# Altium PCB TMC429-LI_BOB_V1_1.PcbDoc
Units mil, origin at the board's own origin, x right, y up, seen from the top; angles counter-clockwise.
Board outline 1000 x 1000 mil, 4 copper layers (Top, GND, SPLY, Bottom), stack 27.719 mil thick; 31 components, 30 nets, 97 pads, 39 vias.
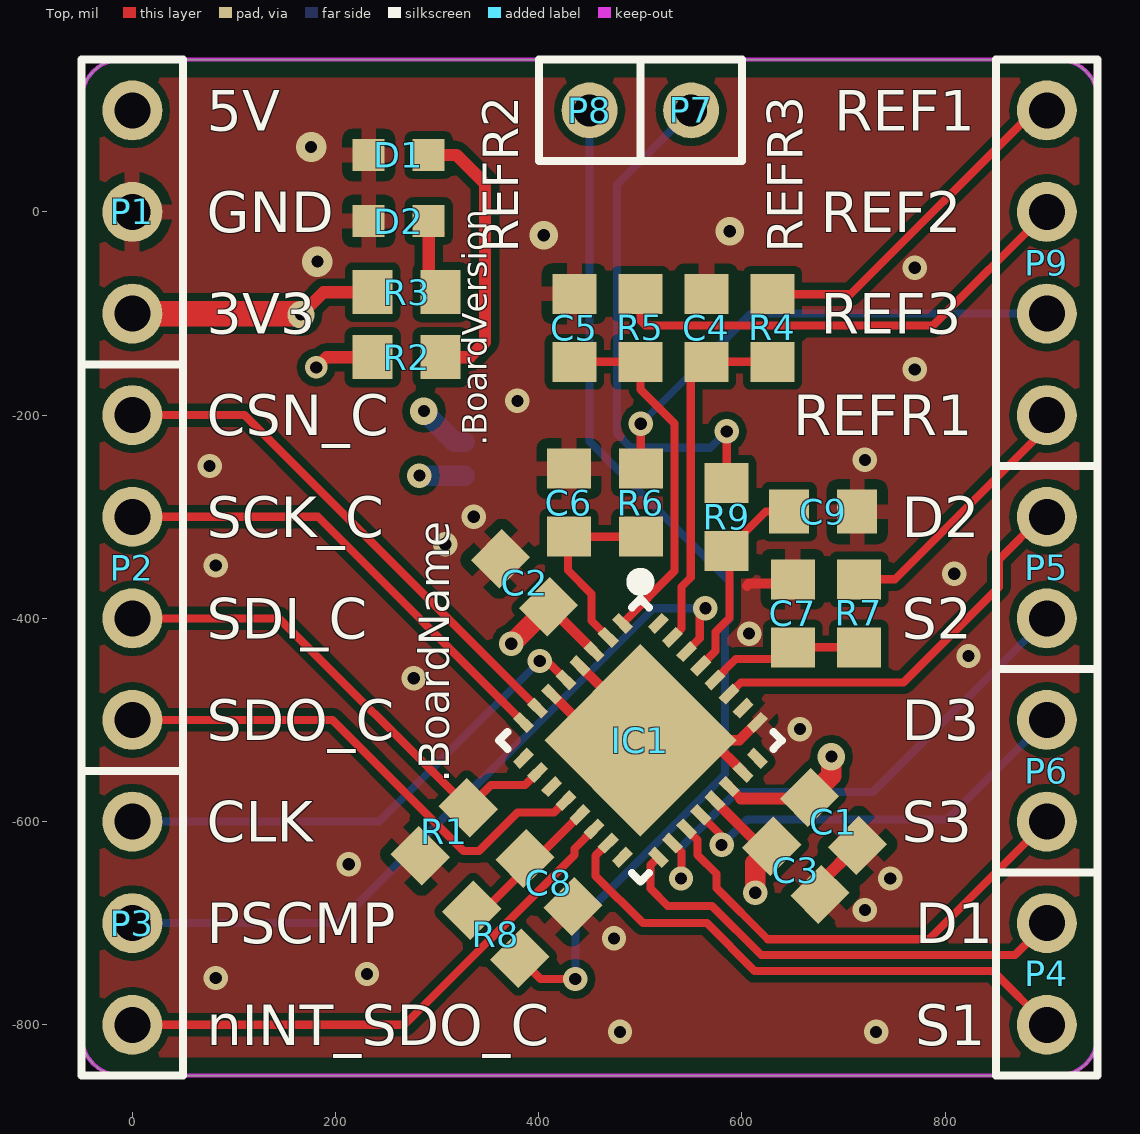
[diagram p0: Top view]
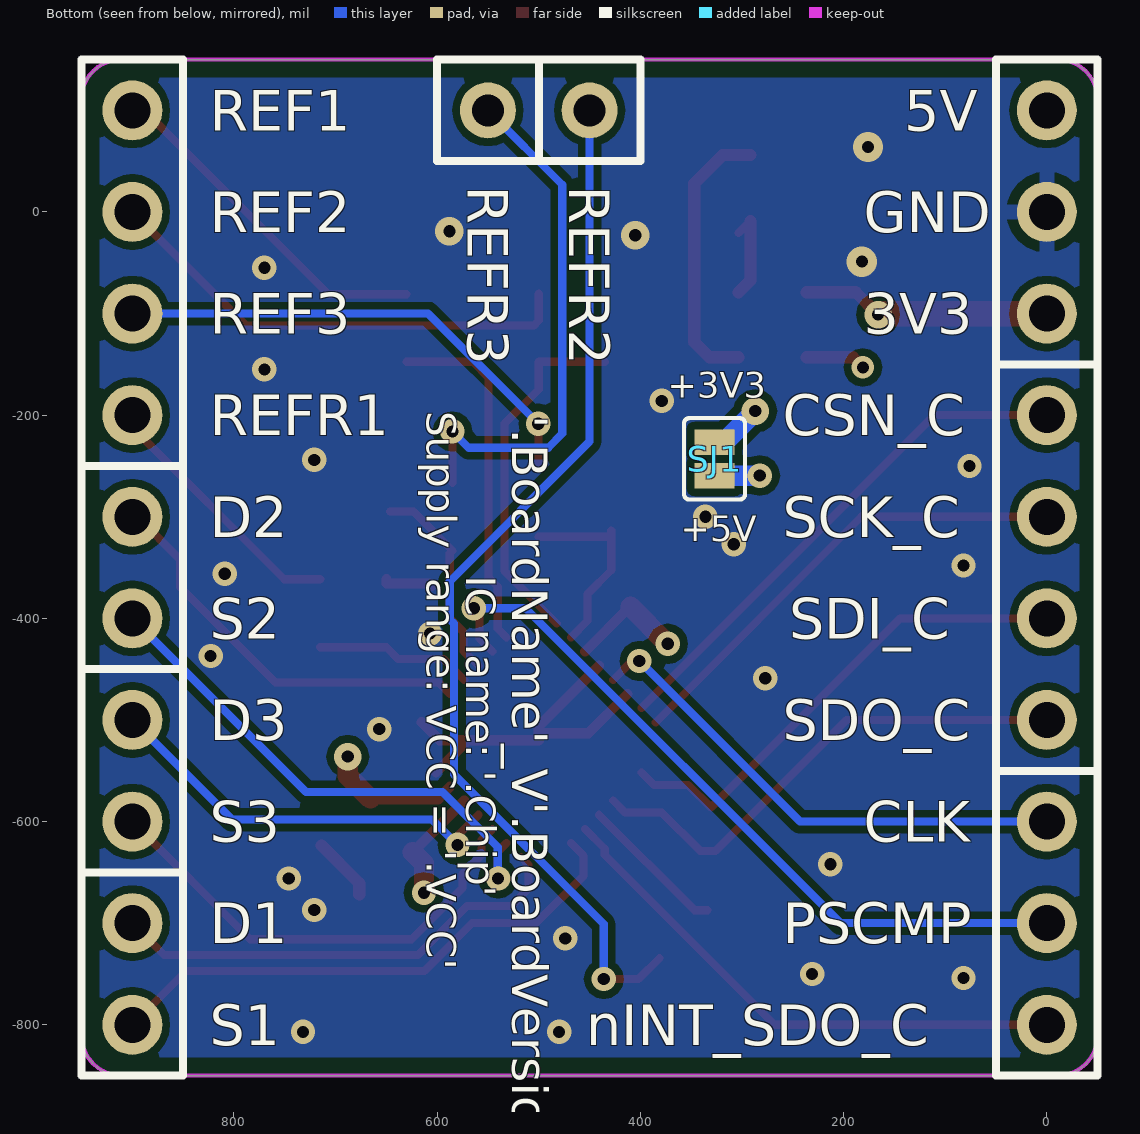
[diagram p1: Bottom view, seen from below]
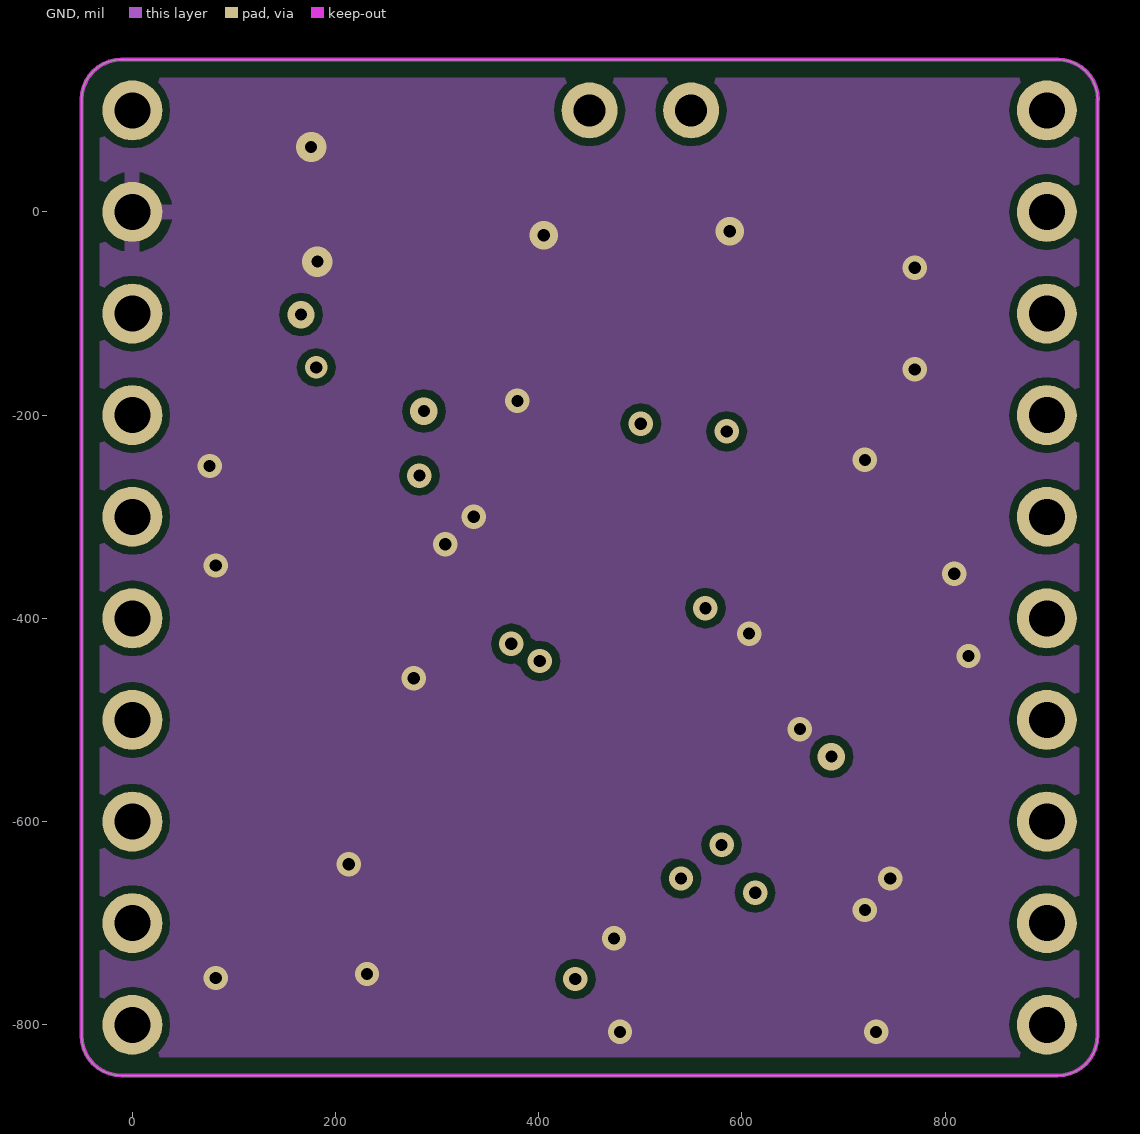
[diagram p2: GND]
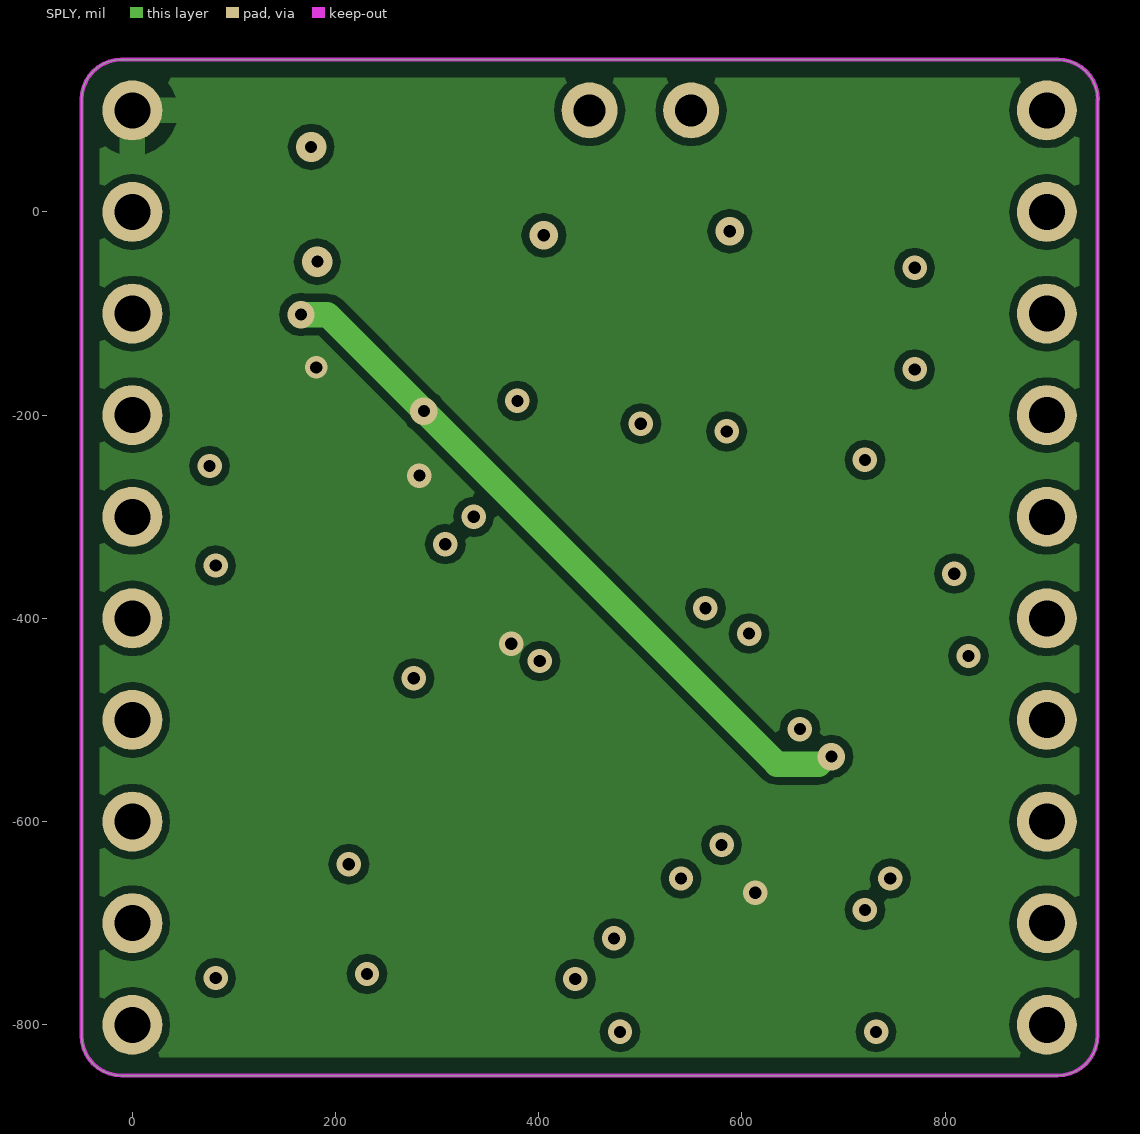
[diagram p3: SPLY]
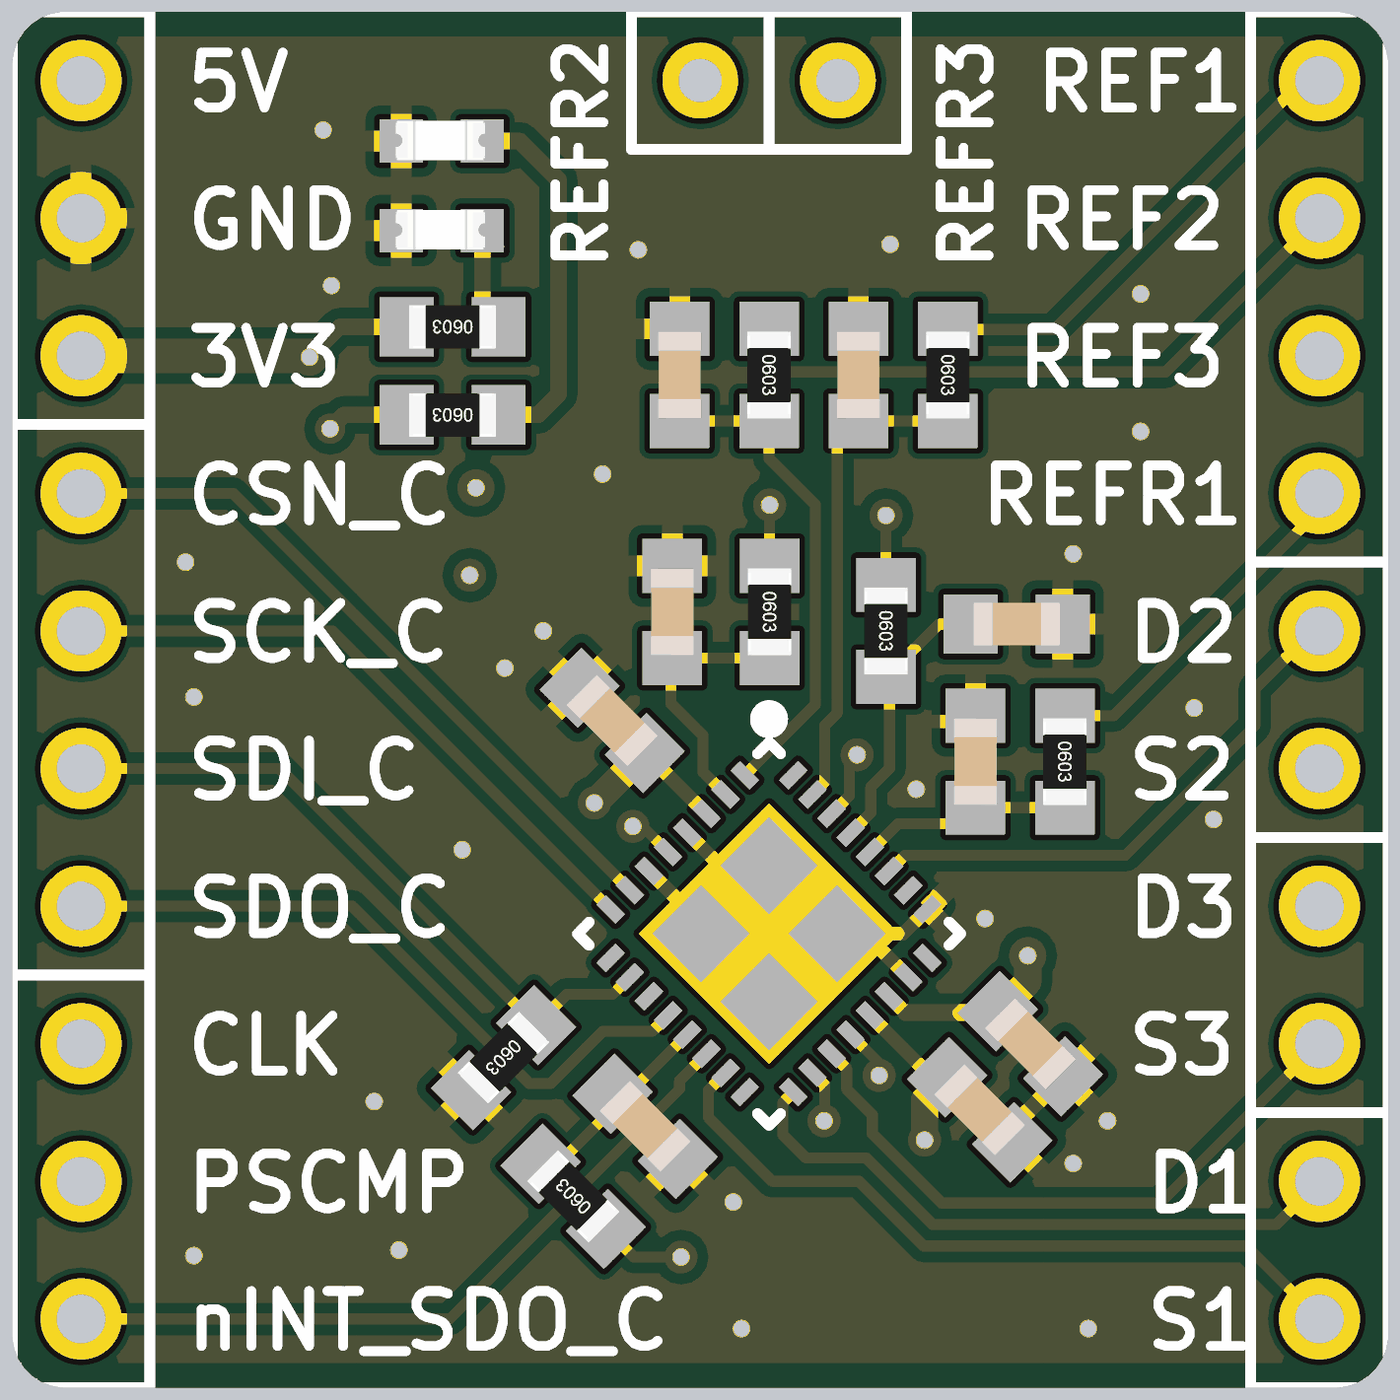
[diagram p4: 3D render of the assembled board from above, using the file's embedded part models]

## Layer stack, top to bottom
Top Solder: solder mask 0.4, Solder Resist, Dk 3.5
Top: signal copper 1.378
Dielectric 1: core 7.874, FR-4, Dk 4.8
GND: signal copper 0.689
Dielectric 2: prepreg 5, FR-4, Dk 4.2
SPLY: signal copper 1.4
Dielectric4: core 10, FR-4, Dk 4.2
Bottom: signal copper 1.378
Bottom Solder: solder mask 0.4, Solder Resist, Dk 3.5

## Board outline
-50,-810.63 ccw(c-10.63,-810.63) -10.63,-850 910.63,-850 ccw(c910.63,-810.63) 950,-810.63 950,110.63 ccw(c910.63,110.63) 910.63,150 -10.63,150 ccw(c-10.63,110.63) -50,110.63

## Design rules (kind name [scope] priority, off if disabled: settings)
Clearance BoardOutlineClearance [OnLayer('Keep-Out Layer')] p1: gap=15.75 ignorepadtopadclearanceinfootprint=FALSE except(0: Arc-Hole Track-Hole SMDPad-Hole THPad-Hole Via-Hole Fill-Hole Poly-Hole Region-Hole Text-Hole)
Clearance "Fiducial Clearance" [HasFootprint('FIDUCIAL_40MIL')] p2: gap=26 ignorepadtopadclearanceinfootprint=FALSE except(0: Arc-Hole Track-Hole SMDPad-Hole THPad-Hole Via-Hole Fill-Hole Poly-Hole Region-Hole Text-Hole)
Clearance [All] p3: gap=7.6 ignorepadtopadclearanceinfootprint=FALSE except(0: Arc-Hole Track-Hole SMDPad-Hole THPad-Hole Via-Hole Fill-Hole Poly-Hole Region-Hole Text-Hole)
ComponentClearance Pinheader2PinheaderClearance [InComponentClass('Pinheader') vs InComponentClass('Pinheader')] p1: gap=0 collisioncheckmode=3 verticalgap=0 showdistances=FALSE
ComponentClearance [All] p2: gap=10 collisioncheckmode=3 verticalgap=10 showdistances=FALSE
DiffPairsRouting [All] p1 off: maxlimit=10 minlimit=7.5 mostfreqgap=10 toplayer_prefgap=7.5 toplayer_minwidth=7.5 toplayer_maxwidth=7.5 toplayer_prefwidth=7.5 midlayer1_prefgap=7.5 midlayer1_minwidth=7.5 midlayer1_maxwidth=7.5 midlayer1_prefwidth=7.5 midlayer2_mingap=10 midlayer2_minwidth=15 midlayer2_maxwidth=15 midlayer2_prefwidth=15 bottomlayer_prefgap=7.5 bottomlayer_minwidth=7.5 bottomlayer_maxwidth=7.5 bottomlayer_prefwidth=7.5 maxuncoupledlength=500
HoleSize [All] p1: absolutevalues=TRUE maxlimit=100000 minlimit=11.81 maxpercent=80.000 minpercent=20.000
HoleToHoleClearance [All] p1: gap=8 allowstackedmicrovias=TRUE
MatchedLengths "SD_CARD MatchedLengths" [InNetClass('SD_CARD')] p1: tolerance=10 checknetsindiffpair=FALSE checkdiffpairvsdiffpair=TRUE checkxsignals=TRUE checkothers=TRUE
MinimumAnnularRing MinimumViaAnnualRing [All] p1: minimumring=4.92
MinimumSolderMaskSliver STM32_MinimumSolderMaskSliver [(InComponent('STM1') AND InComponent('STM2')) vs (InComponent('STM1') AND InComponent('STM2'))] p1: minsoldermaskwidth=1
MinimumSolderMaskSliver USB_HUB_MinimumSolderMaskSliver [InComponent('USB_HUB')] p2: minsoldermaskwidth=1
MinimumSolderMaskSliver [All] p3 off: minsoldermaskwidth=1.5
PasteMaskExpansion TestPadPasteMaskExpansion [HasFootprint('SMD_TP_2X2_ROUND')] p1: expansion=-78.74
PasteMaskExpansion [All] p2: expansion=0
PlaneConnect VM_PlaneConnect [OnLayer('VM') AND InNet('VM')] p1: planeconnectstyle=Relief reliefexpansion=20 reliefentries=4 reliefconductorwidth=20 reliefairgap=10
PlaneConnect [All] p2: planeconnectstyle=Relief reliefexpansion=20 reliefentries=4 reliefconductorwidth=10 reliefairgap=10
PolygonConnect VSA_C1_ConnectStyle [InNet('VM') AND inComponent('C1')] p1: connectstyle=Direct reliefconductorwidth=20 reliefentries=4 polygonreliefangle="90 Angle" airgapwidth=8
PolygonConnect ViaConnectStyle [IsVia] p2: connectstyle=Direct reliefconductorwidth=20 reliefentries=4 polygonreliefangle="90 Angle" airgapwidth=8
PolygonConnect 5V_ConnectStyle [InNet('+5V')] p3: connectstyle=Relief reliefconductorwidth=25 reliefentries=4 polygonreliefangle="90 Angle" airgapwidth=15
PolygonConnect MotorPhaceConnectStyle [(IsVia OR IsPad) AND InNetClass('MotorPower')] p4: connectstyle=Direct reliefconductorwidth=10 reliefentries=4 polygonreliefangle="90 Angle" airgapwidth=10
PolygonConnect ThermalVias [IsVia] p5: connectstyle=Direct reliefconductorwidth=10 reliefentries=4 polygonreliefangle="90 Angle" airgapwidth=10
PolygonConnect [All] p6: connectstyle=Relief reliefconductorwidth=15 reliefentries=4 polygonreliefangle="90 Angle" airgapwidth=10
RoutingVias [All] p1: holewidth=12 width=24 viastyle="Through Hole" minholewidth=12 minwidth=22 maxholewidth=12 maxwidth=50
ShortCircuit [All] p1 off: allowed=FALSE
SilkToBoardRegionClearance [All] p1 off:
SilkToSilkClearance [All] p1 off: silktosilkclearance=10
SilkToSolderMaskClearance [IsPad] p1 off: minsilkscreentomaskgap=10 clearancetoexposedcopper=TRUE
SolderMaskExpansion FiducialSolderMaskExpansion [HasFootprint('FIDUCIAL_40MIL')] p1: expansion=26
SolderMaskExpansion [All] p2: expansion=4
UnRoutedNet [All] p1 off:
Width Other_Width [All] p1: maxlimit=100000 minlimit=8 preferedwidth=11.81 minimp=50.000000 maximp=50.000000 favimp=50.000000
18 further rules are at their usual default settings.

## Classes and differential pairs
differential pair class USB_DIFF: STM_USB STM_USB_D

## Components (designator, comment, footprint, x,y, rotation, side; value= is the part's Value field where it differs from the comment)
C1 "470nF/16V/10%" C0603 690,-600 r315 top
C2 "100nF/16V/10%" C0603 386,-365 r135 top
C3 "100nF/16V/10%" C0603 653,-648 r315 top
C4 "10nF/16V/10%" C0603 565,-114 r90 top
C5 "10nF/16V/10%" C0603 435,-114 r90 top
C6 "10nF/16V/10%" C0603 429.72,-286.17 r90 top
C7 "10nF/16V/10%" C0603 650.01,-395 r90 top
C8 "10nF/16V/10%" C0603 410,-660 r315 top
C9 "10nF/16V/10%" C0603 680,-295 r0 top
D1 "LED, Blue, SMD, 20mA, 2.8V, 465 nm" LED_0603 262.13,56 r180 top
D2 "LED, Blue, SMD, 20mA, 2.8V, 465 nm" LED_0603 262.13,-9 r180 top
IC1 "TMC429-LI" TMC429_QFN32_0.5_5.0X5.0 500,-520 r225 top
P1 "PWR" 3_PIN_THT 0,-100 r0 top
P2 "SPI" 4_PIN_THT 0,-200 r180 top
P3 "MISC" 3_PIN_THT 0,-800 r0 top
P4 "S/D_1" 2_PIN_THT 900,-800 r0 top
P5 "S/D_2" 2_PIN_THT 900,-400 r0 top
P6 "S/D_3" 2_PIN_THT 900,-600 r0 top
P7 "REFR3" TH_PIN 550,100 r0 top
P8 "REFR2" TH_PIN 450,100 r0 top
P9 "REF" 4_PIN_THT 900,-200 r0 top
R1 "10k" R0603 307,-610 r225 top
R2 "1k" R0603 270.01,-142.99 r180 top
R3 "1k" R0603 270.01,-78.99 r180 top
R4 "4k7" R0603 630,-114 r270 top
R5 "4k7" R0603 500,-114 r270 top
R6 "4k7" R0603 500.43,-286.17 r270 top
R7 "4k7" R0603 715.01,-395 r270 top
R8 "4k7" R0603 357.68,-710.9 r135 top
R9 "4k7" R0603 585,-300 r270 top
SJ1 "SPI_MODE" SJ_SMALL_2PIN_1X0.635 327,-243 r270 bottom

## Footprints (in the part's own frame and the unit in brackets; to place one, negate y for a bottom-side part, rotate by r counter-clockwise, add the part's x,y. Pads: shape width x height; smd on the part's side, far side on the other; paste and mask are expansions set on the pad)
2_PIN_THT [mm]
  round 1.5 hole 0.9: 1(0,0) 2(0,2.54)
  silkscreen extent -1.27,-1.27 1.27,3.81
3_PIN_THT [mm]
  round 1.5 hole 0.9: 1(0,0) 2(0,2.54) 3(0,5.08)
  silkscreen extent -1.27,-1.27 1.27,6.35
4_PIN_THT [mm]
  round 1.5 hole 0.9: 1(0,0) 2(0,2.54) 3(0,5.08) 4(0,7.62)
  silkscreen extent -1.27,-1.27 1.27,8.89
C0603 [mm] "0603 ceramic capacitor"
  rect 1x1.1 smd: 1(-0.85,0) 2(0.85,0)
  body extent -0.8,-0.4 0.8,0.4, height 0.8
LED_0603 [mm]
  rect 0.8x0.8 smd: 1(-0.75,0) 2(0.75,0)
  body extent -0.8,-0.38 0.85,0.35, height 0.68
R0603 [mm] "0603 resistor"
  rect 1x1.1 smd: 1(-0.85,0) 2(0.85,0)
  body extent -0.8,-0.4 0.8,0.4, height 0.45
SJ_SMALL_2PIN_1X0.635 [mil]
  rect 25x39.37 smd: 1(-16.5,0) 2(16.5,0)
  silkscreen extent -40,-30 40,30
TH_PIN [mm]
  round 1.4 hole 0.8: 1(0,0)
  silkscreen extent -1.27,-1.27 1.27,1.27
TMC429_QFN32_0.5_5.0X5.0 [mm]
  rect 0.254x0.5 smd: 1(-1.75,-2.385) 2(-1.25,-2.385) 3(-0.75,-2.385) 4(-0.25,-2.385) 5(0.25,-2.385) 6(0.75,-2.385) 7(1.25,-2.385) 8(1.75,-2.385) 17(1.75,2.385) 18(1.25,2.385) 19(0.75,2.385) 20(0.25,2.385) 21(-0.25,2.385) 22(-0.75,2.385) 23(-1.25,2.385) 24(-1.75,2.385)
  rect 0.5x0.254 smd: 9(2.385,-1.75) 10(2.385,-1.25) 11(2.385,-0.75) 12(2.385,-0.25) 13(2.385,0.25) 14(2.385,0.75) 15(2.385,1.25) 16(2.385,1.75) 25(-2.385,1.75) 26(-2.385,1.25) 27(-2.385,0.75) 28(-2.385,0.25) 29(-2.385,-0.25) 30(-2.385,-0.75) 31(-2.385,-1.25) 32(-2.385,-1.75)
  rect 3.4x3.4 smd paste-25.4: 33(0,0)
  silkscreen extent -2.9,-2.9 2.5,2.5, body extent -2.5,-2.5 2.5,2.5, height 0.9

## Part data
C1: library part Capacitor, "Ceramic capacitor", Capacitance=470nF, MPN=MC0603X474K160CT, VoltageRating=16V
C2 C3: library part Capacitor, "Ceramic capacitor", Capacitance=100nF, MPN=MC0603B104K160CT, VoltageRating=16V
C4 C5 C6 C7 C8 C9: library part Capacitor, "Ceramic capacitor", Capacitance=10nF, MPN=MC0603B103K160CT, VoltageRating=16V
D1 D2: Colour=Blue, Current rating=20mA, MPN=LTST-C191TBKT-5A
IC1: "Intelligent Triple Stepper Motor Controller with SPI, Step/Dir, QFN32(5x5)"
P1 P3: library part "Header 3", "Header, 3-Pin"
P2 P9: library part "Header 4", "Header, 4-Pin"
P4 P5 P6: library part "Header 2", "Header, 2-Pin"
P7 P8: library part PIN
R1: library part "10 kohm, 50 V, 0603 [1608 Metric], 63 mW, ± 1%, MC Series", "10 kohm, 50 V, 0603 [1608 Metric], 63 mW, ± 1%, MC Series", MPN=MC0063W0603110K, PowerRating=63mW, Temp coefficient=*ppm, VoltageRating=50V
R2 R3: library part "1 kohm, 50 V, 0603 [1608 Metric], 63 mW, ± 1%, MC Series", "1 kohm, 50 V, 0603 [1608 Metric], 63 mW, ± 1%, MC Series", MPN=MC0063W060311K, PowerRating=63mW, Temp coefficient=*ppm, VoltageRating=50V
R4 R5 R6 R7 R8 R9: library part "4.7 kohm, 50 V, 0603 [1608 Metric], 63 mW, ± 1%, MC Series", "4.7 kohm, 50 V, 0603 [1608 Metric], 63 mW, ± 1%, MC Series", MPN=MC0063W060314K7, PowerRating=63mW, Temp coefficient=*ppm, VoltageRating=50V
SJ1: library part SJ, "SMD solder <b>JUMPER</b>"

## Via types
v1: diameter 24, hole 12, Top to Bottom, tented both sides, 31 vias
v2: diameter 27, hole 12, Top to Bottom, tented both sides, 3 vias
v3: diameter 29.81, hole 11.81, Top to Bottom, tented both sides, 2 vias
v4: diameter 28, hole 12, Top to Bottom, tented both sides, 2 vias
v5: diameter 22, hole 12, Top to Bottom, tented both sides, 1 vias

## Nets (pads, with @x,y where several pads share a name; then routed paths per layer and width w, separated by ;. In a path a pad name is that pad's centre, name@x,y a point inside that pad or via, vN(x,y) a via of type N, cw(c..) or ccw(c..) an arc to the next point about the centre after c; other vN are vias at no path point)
+3V3: C1.1 IC1.22 P1.1 R3.2 SJ1.1 | length 1125.3
  Top w10: IC1.22 599.1,-577.34
  Top w12: v2(166,-101) 188.01,-78.99 R3.2 ; 599.1,-577.34 C1.1@665.66,-577.34
  Top w20: C1.1@665.66,-577.34 688,-555 v2(688,-536)
  Top w25: P1.1 165,-100 v2(166,-101)
  SPLY w25: v2(166,-101) 192,-101 v2(287,-196) 634.43,-543.43 675.43,-543.43
  Bottom w20: v2(287,-196) 317.5,-226.5 SJ1.1
+5V: C2.1 C3.1 IC1.3 IC1.21 P1.3 R2.2 SJ1.2 | length 335.1
  Top w8: v1(373,-425) v1@373.33,-425 ; C2.1 C2.1@410.42,-388.66
  Top w10: C2.1@410.42,-388.66 IC1.3 ; IC1.21 C3.1@624,-630.08
  Top w12: v5(181,-153) 191.01,-142.99 R2.2
  Top w20: v1@373.33,-425 C2.1 ; v1(613,-670) 613,-641.08 C3.1@624,-630.08
  Bottom w20: v1(282.5,-259.5) SJ1.2
CLK: IC1.5 P3.3 | length 499.8
  Top w8: v1(401,-442) 408.08,-442 IC1.5
  Bottom w8: P3.3 243,-600 v1(401,-442)
CSN_C: IC1.7 P2.1 | length 518.3
  Top w8: P2.1 110.4,-200 IC1.7
D1: IC1.17 P4.2 | length 464.2
  Top w8: IC1.17 510,-642.79 510,-666 527,-683 570.56,-683 618.96,-731.4 868.6,-731.4 P4.2
D2: IC1.27 P5.2 | length 400.8
  Top w8: IC1.27 598.76,-463 759,-463 853,-369 853,-342 895,-300 P5.2
D3: IC1.20 P6.2 | length 409.1
  Top w8: IC1.20 580,-613.92 v1(580,-623)
  Bottom w8: v1(580,-623) 605,-598 802,-598 P6.2
GND: C1.2 C2.2 C3.2 C4.2 C5.2 C6.2 C7.2 C8.2 C9.2 D1.2 D2.2 IC1.4 IC1.6 IC1.23 IC1.25 IC1.33 P1.2 R1.2 | length 481.8
  Top w10: IC1.6 451.28,-513.04 IC1.33@500,-513.04 ; IC1.4 500,-506.08 IC1.33@500,-513.04 ; IC1.23 IC1.33@569.6,-520 ; 605,-368 607.25,-365.75 650.01,-365.75 C7.2 ; IC1.25 597.44,-520 IC1.33@569.6,-520 ; IC1.33@500,-513.04 IC1.33 555.68,-520 IC1.33@569.6,-520
  Top w12: C3.2 676.66,-660.66 C1.2
  other v1: 480,-807 732,-807 82,-754 231,-750 474,-715 721,-687 746,-656 213,-642 657,-509 277,-459 823,-437 607,-415 809,-356 82,-348 308,-327 336,-300 76,-250 721,-244 379,-186 770,-155 770,-55
  other v3: 182,-49 176,64
  other v4: 405,-23 588,-19
NetD1_1: D1.1 R2.1 | length 272.7
  Top w12: D1.1 319,56 347,28 347,-128 332.01,-142.99 R2.1
NetD2_1: D2.1 R3.1 | length 91.6
  Top w8: D2.1 D2.1@303.47,-20.81
  Top w12: D2.1 291.66,-67.18 R3.1
NINT_SDO_C: IC1.14 P3.1 | length 538
  Top w8: P3.1 268,-800 435,-633 435,-626.76 IC1.14
PSCMP: IC1.30 P3.2 | length 742.8
  Top w8: IC1.30 558.4,-419.84 558.4,-395.6 v1(564,-390)
  Bottom w8: P3.2 203,-700 513,-390 v1(564,-390)
REF1: C4.1 IC1.31 R4.2 | length 350.2
  Top w8: IC1.31 540.4,-410 540.4,-368.87 549.6,-359.67 549.6,-162.86 C4.1 R4.2
REF1IN: P9.4 R4.1 | length 345
  Top w8: R4.1@630,-81 707,-81 888,100 P9.4
REF2: C5.1 IC1.1 R5.2 | length 357.7
  Top w8: C5.1 R5.2 500,-174.62 533.68,-208.31 533.68,-353.53 IC1.1
REF2IN: P9.3 R5.1 | length 474.8
  Top w8: R5.1 500,-107 504.82,-111.82 788.18,-111.82 P9.3
REF3: C6.1 IC1.2 R6.2 | length 192.3
  Top w8: C6.1@428.67,-313.66 428.67,-352.67 452,-376 452,-402.4 IC1.2 ; C6.1 R6.2
REF3IN: P9.2 R6.1 | length 488.8
  Top w8: R6.1 v1(500.43,-208.43)
  Bottom w8: v1(500.43,-208.43) 608.86,-100 P9.2
REFR1: C7.1 IC1.28 R7.2 | length 154.9
  Top w8: IC1.28 593.92,-440 638.47,-440 C7.1 R7.2
REFR1IN: P9.1 R7.1 | length 258.9
  Top w8: R7.1 750.47,-361.53 900,-212 P9.1
REFR2: C8.1 IC1.13 R8.2 | length 145.4
  Top w8: R8.2 346.68,-687.24 IC1.13
REFR2IN: P8.1 R8.1 | length 1037.9
  Top w8: R8.1 401.78,-755 v1(436,-755)
  Bottom w8: v1(436,-755) 436,-701 583.4,-553.6 583.4,-405.22 587.6,-401.02 587.6,-363.6 450,-226 P8.1
REFR3: C9.1 IC1.29 R9.2 | length 203.4
  Top w8: IC1.29 574,-432.08 574,-413.38 587.6,-399.78 587.6,-336.06 R9.2 623.46,-295 C9.1
REFR3IN: P7.1 R9.1 | length 519.6
  Top w8: R9.1 v1(585,-216)
  Bottom w8: P7.1 476.83,26.83 476.83,-218.2 490.65,-232.03 568.97,-232.03 v1(585,-216)
S1: IC1.15 P4.1 | length 542.1
  Top w8: IC1.15 456,-633.6 456,-653.44 502.56,-700 565.5,-700 612.5,-747 847,-747 P4.1
S2: IC1.18 P5.1 | length 522.4
  Top w8: IC1.18 540.4,-630 540.4,-649.6 540,-650 v1(540,-656)
  Bottom w8: v1(540,-656) 540,-650 540.4,-649.6 540.4,-625.22 594.62,-571 729,-571 P5.1
S3: IC1.19 P6.1 | length 476.9
  Top w8: IC1.19 556.4,-618.16 556.4,-632.78 575,-651.38 575,-665.38 625.42,-715.8 784.2,-715.8 P6.1
  Bottom w8: P6.1@897,-598 P6.1@906,-607
SCK_C: IC1.8 P2.2 | length 468.7
  Top w8: P2.2 182.56,-300 IC1.8
SDI_C: IC1.10 P2.3 R1.1 | length 490.4
  Top w8: P2.3 144.33,-400 R1.1 353,-564 386.4,-564 IC1.10
SDO_C: IC1.12 P2.4 | length 500.6
  Top w8: P2.4 197,-500 326,-629 341,-629 379,-591 415.08,-591 IC1.12
pads on no net: IC1.9 IC1.11 IC1.16 IC1.24 IC1.26 IC1.32

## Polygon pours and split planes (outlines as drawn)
GND on Bottom "BTM_GND" (solid, pour order 8): -50,-810.63 -50,110.63 cw(c-10.63,110.63) -10.63,150 910.63,150 910.97,150 cw(c910.97,110.63) 950.34,110.63 950,110.63 950,-810.63 cw(c910.63,-810.63) 910.63,-850 -10.63,-850 cw(c-10.63,-810.63)
GND on GND "BTM_GND" (solid, pour order 7): -50,-810.63 -50,110.63 cw(c-10.63,110.63) -10.63,150 910.63,150 910.97,150 cw(c910.97,110.63) 950.34,110.63 950,110.63 950,-810.63 cw(c910.63,-810.63) 910.63,-850 -10.63,-850 cw(c-10.63,-810.63)
GND on Top "BTM_GND" (solid, pour order 6): -50,-810.63 -50,110.63 cw(c-10.63,110.63) -10.63,150 910.63,150 910.97,150 cw(c910.97,110.63) 950.34,110.63 950,110.63 950,-810.63 cw(c910.63,-810.63) 910.63,-850 -10.63,-850 cw(c-10.63,-810.63)
+5V on SPLY "BTM_GND" (solid, pour order 5): -50,-810.63 -50,110.63 cw(c-10.63,110.63) -10.63,150 910.63,150 910.97,150 cw(c910.97,110.63) 950.34,110.63 950,110.63 950,-810.63 cw(c910.63,-810.63) 910.63,-850 -10.63,-850 cw(c-10.63,-810.63)

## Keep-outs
Keep-Out Layer:
  the board outline again, w4

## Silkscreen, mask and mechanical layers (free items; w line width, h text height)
Top Overlay:
  text "5V" at 73.45,80.01 h40
  text "REF1" at 690.71,80.01 h40
  text "GND" at 73.45,-19.99 h40
  text "REF2" at 677.38,-19.99 h40
  text "REFR2" at 380,-40 h35 r90
  text "REFR3" at 660,-40 h35 r90
  text "3V3" at 73.45,-119.99 h40
  text "REF3" at 677.38,-119.99 h40
  text "CSN_C" at 73.45,-219.99 h40
  text "REFR1" at 650.72,-219.99 h40
  text ".BoardVersion" at 349,-230.11 h24 r90
  text "SCK_C" at 73.45,-319.99 h40
  text "D2" at 757.35,-319.99 h40
  text "SDI_C" at 73.45,-419.99 h40
  text "S2" at 757.35,-419.99 h40
  text "SDO_C" at 73.45,-519.99 h40
  text "D3" at 757.35,-519.99 h40
  text ".BoardName" at 312,-562 h30 r90
  text "CLK" at 73.45,-619.99 h40
  text "S3" at 757.35,-619.99 h40
  text "PSCMP" at 73.45,-719.99 h40
  text "D1" at 770.68,-719.99 h40
  text "nINT_SDO_C" at 73.45,-819.99 h40
  text "S1" at 770.68,-819.99 h40
Bottom Overlay:
  text "5V" at 140.09,80.01 h40
  text "REF1" at 824,80.01 h40
  text "REFR2" at 469.99,26 h40 r90
  text "REFR3" at 569.99,26 h40 r90
  text "GND" at 180.08,-19.99 h40
  text "REF2" at 824,-19.99 h40
  text "3V3" at 180.08,-119.99 h40
  text "REF3" at 824,-119.99 h40
  text "+3V3" at 372.82,-183 h25
  text "Supply range: VCC = '.VCC'" at 620.05,-196.1 h50 r90
  text "'.BoardName'_V'.BoardVersion'" at 526,-200 h35 r90
  text "CSN_C" at 260.05,-219.99 h40
  text "REFR1" at 824,-219.99 h40
  text "SCK_C" at 260.05,-319.99 h40
  text "D2" at 824,-319.99 h40
  text "+5V" at 360.32,-324 h25
  text "IC name: '.Chip'" at 581,-358.07 h50 r90
  text "SDI_C" at 253.39,-419.99 h40
  text "S2" at 824,-419.99 h40
  text "SDO_C" at 260.05,-519.99 h40
  text "D3" at 824,-519.99 h40
  text "CLK" at 180.08,-619.99 h40
  text "S3" at 824,-619.99 h40
  text "PSCMP" at 260.05,-719.99 h40
  text "D1" at 824,-719.99 h40
  text "nINT_SDO_C" at 453.32,-819.99 h40
  text "S1" at 824,-819.99 h40
TopAsm:
  text ".BoardVersion" at 166.06,-73 h50 r90
  text ".BoardName" at 166.06,-757 h50 r90

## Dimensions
-50,110.63 to 950,110.63 on Dimension
910.63,-850 to 910.63,150 on Dimension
